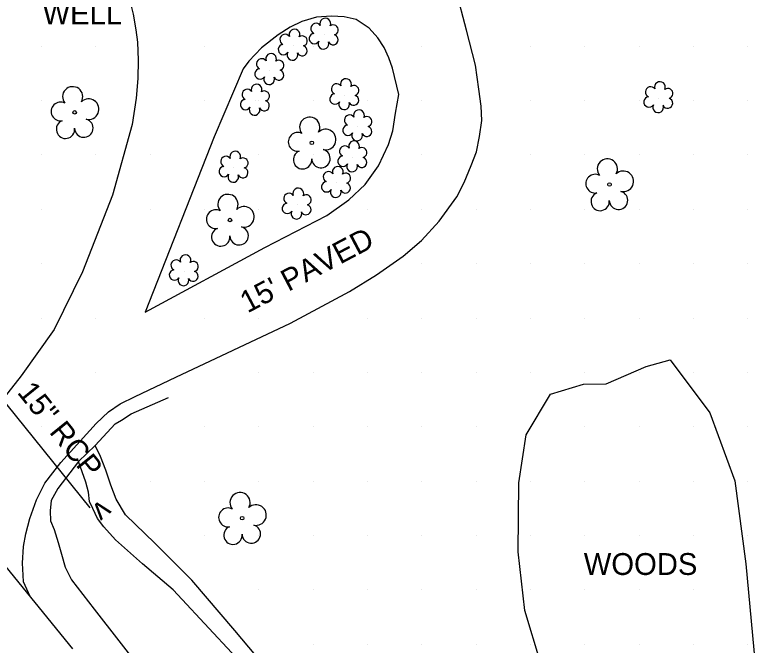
# Model space of a CAD drawing. Extents: x 1548934 to 1561348, y 809680 to 824075.
# Drawn here: x 1552285.1 to 1552421.7, y 809979.7 to 810095.7 of the extents above; entities that cross this region are included whole.
import ezdxf

# ---------------------------------------------------------------- set-up
doc = ezdxf.new("R2010")
doc.units = 0
for name, color, linetype in [('E_NCDOT_Vertical_Profile_Ground_Line', 7, 'Continuous'), ('Exist DTM QL2 LIDAR Elevation Point', 7, 'Continuous'), ('Exist Other Culture Well Text', 7, 'Continuous'), ('Exist Roads EOP Other Text', 7, 'Continuous'), ('Exist Structure Minor Culvert Topo', 7, 'Continuous'), ('Exist Structure Minor Culvert Topo Terminator', 7, 'Continuous'), ('Exist Structure Minor Pipes RCP 15 Inch Text', 7, 'Continuous'), ('Exist Vegetation Shrub CELL', 7, 'Continuous'), ('Exist Vegetation Tree CELL', 7, 'Continuous'), ('Exist Vegetation Woods Line', 7, 'Continuous'), ('Exist Vegetation Woods Line Text', 7, 'Continuous'), ('P_RDY_Paved_Shoulder', 7, 'Continuous'), ('PH Exist DTM Breakline', 7, 'Continuous')]:
    doc.layers.add(name, color=color, linetype=linetype)

msp = doc.modelspace()

# ---------------------------------------------------------------- linework, layer by layer
at = {"layer": 'E_NCDOT_Vertical_Profile_Ground_Line'}
msp.add_line((1552295.81, 809979.05), (1552269.12, 810011.85), dxfattribs=at)
at = {"layer": 'Exist DTM QL2 LIDAR Elevation Point'}
for p, q in [((1552290.04, 810089.94), (1552290.04, 810089.94)), ((1552300.04, 810089.94), (1552300.04, 810089.94)), ((1552320.04, 810089.94), (1552320.04, 810089.94)), ((1552340.05, 810089.94), (1552340.05, 810089.94)), ((1552360.05, 810089.94), (1552360.05, 810089.94)), ((1552380.05, 810089.94), (1552380.05, 810089.94)), ((1552390.05, 810089.94), (1552390.05, 810089.94)), ((1552400.05, 810089.94), (1552400.05, 810089.94)), ((1552410.05, 810089.94), (1552410.05, 810089.94)), ((1552420.05, 810089.94), (1552420.05, 810089.94)), ((1552290.04, 810079.94), (1552290.04, 810079.94)), ((1552300.04, 810079.94), (1552300.04, 810079.94)), ((1552320.04, 810079.94), (1552320.04, 810079.94)), ((1552330.05, 810079.94), (1552330.05, 810079.94)), ((1552340.05, 810079.94), (1552340.05, 810079.94)), ((1552350.05, 810079.94), (1552350.05, 810079.94)), ((1552360.05, 810079.94), (1552360.05, 810079.94)), ((1552380.05, 810079.94), (1552380.05, 810079.94)), ((1552390.05, 810079.94), (1552390.05, 810079.94)), ((1552400.05, 810079.94), (1552400.05, 810079.94)), ((1552410.05, 810079.94), (1552410.05, 810079.94)), ((1552420.05, 810079.94), (1552420.05, 810079.94)), ((1552290.04, 810069.94), (1552290.04, 810069.94)), ((1552300.04, 810069.94), (1552300.04, 810069.94)), ((1552310.04, 810069.94), (1552310.04, 810069.94)), ((1552330.05, 810069.94), (1552330.05, 810069.94)), ((1552340.05, 810069.94), (1552340.05, 810069.94)), ((1552360.05, 810069.94), (1552360.05, 810069.94)), ((1552380.05, 810069.94), (1552380.05, 810069.94)), ((1552390.05, 810069.94), (1552390.05, 810069.94)), ((1552400.05, 810069.94), (1552400.05, 810069.94)), ((1552410.05, 810069.94), (1552410.05, 810069.94)), ((1552420.05, 810069.94), (1552420.05, 810069.94)), ((1552290.04, 810059.94), (1552290.04, 810059.94)), ((1552310.04, 810059.94), (1552310.04, 810059.94)), ((1552320.04, 810059.94), (1552320.04, 810059.94)), ((1552330.05, 810059.94), (1552330.05, 810059.94)), ((1552350.05, 810059.94), (1552350.05, 810059.94)), ((1552360.05, 810059.94), (1552360.05, 810059.94)), ((1552370.05, 810059.94), (1552370.05, 810059.94)), ((1552380.05, 810059.94), (1552380.05, 810059.94)), ((1552390.05, 810059.94), (1552390.05, 810059.94)), ((1552400.05, 810059.94), (1552400.05, 810059.94)), ((1552410.05, 810059.94), (1552410.05, 810059.94)), ((1552420.05, 810059.94), (1552420.05, 810059.94)), ((1552290.04, 810049.94), (1552290.04, 810049.94)), ((1552340.05, 810049.94), (1552340.05, 810049.94)), ((1552360.05, 810049.94), (1552360.05, 810049.94)), ((1552370.05, 810049.94), (1552370.05, 810049.94)), ((1552380.05, 810049.94), (1552380.05, 810049.94)), ((1552390.05, 810049.94), (1552390.05, 810049.94)), ((1552400.05, 810049.94), (1552400.05, 810049.94)), ((1552410.05, 810049.94), (1552410.05, 810049.94)), ((1552420.05, 810049.94), (1552420.05, 810049.94)), ((1552290.04, 810039.93), (1552290.04, 810039.93)), ((1552300.04, 810039.93), (1552300.04, 810039.93)), ((1552320.04, 810039.93), (1552320.04, 810039.93)), ((1552330.05, 810039.93), (1552330.05, 810039.93)), ((1552350.05, 810039.93), (1552350.05, 810039.93)), ((1552360.05, 810039.93), (1552360.05, 810039.93)), ((1552370.05, 810039.93), (1552370.05, 810039.93)), ((1552380.05, 810039.93), (1552380.05, 810039.93)), ((1552390.05, 810039.93), (1552390.05, 810039.93)), ((1552400.05, 810039.93), (1552400.05, 810039.93)), ((1552410.05, 810039.93), (1552410.05, 810039.93)), ((1552420.05, 810039.93), (1552420.05, 810039.93)), ((1552300.04, 810029.93), (1552300.04, 810029.93)), ((1552330.05, 810029.93), (1552330.05, 810029.93)), ((1552340.05, 810029.93), (1552340.05, 810029.93)), ((1552350.05, 810029.93), (1552350.05, 810029.93)), ((1552360.05, 810029.93), (1552360.05, 810029.93)), ((1552370.05, 810029.93), (1552370.05, 810029.93)), ((1552380.05, 810029.93), (1552380.05, 810029.93)), ((1552390.05, 810029.93), (1552390.05, 810029.93)), ((1552400.05, 810029.93), (1552400.05, 810029.93)), ((1552410.05, 810029.93), (1552410.05, 810029.93)), ((1552420.05, 810029.93), (1552420.05, 810029.93)), ((1552290.04, 810019.93), (1552290.04, 810019.93)), ((1552320.04, 810019.93), (1552320.04, 810019.93)), ((1552330.05, 810019.93), (1552330.05, 810019.93)), ((1552340.05, 810019.93), (1552340.05, 810019.93)), ((1552350.05, 810019.93), (1552350.05, 810019.93)), ((1552360.05, 810019.93), (1552360.05, 810019.93)), ((1552370.05, 810019.93), (1552370.05, 810019.93)), ((1552380.05, 810019.93), (1552380.05, 810019.93)), ((1552390.05, 810019.93), (1552390.05, 810019.93)), ((1552400.05, 810019.93), (1552400.05, 810019.93)), ((1552410.05, 810019.93), (1552410.05, 810019.93)), ((1552420.05, 810019.93), (1552420.05, 810019.93)), ((1552310.04, 810009.93), (1552310.04, 810009.93)), ((1552320.04, 810009.93), (1552320.04, 810009.93)), ((1552330.05, 810009.93), (1552330.05, 810009.93)), ((1552340.05, 810009.93), (1552340.05, 810009.93)), ((1552350.05, 810009.93), (1552350.05, 810009.93)), ((1552360.05, 810009.93), (1552360.05, 810009.93)), ((1552370.05, 810009.93), (1552370.05, 810009.93)), ((1552380.05, 810009.93), (1552380.05, 810009.93)), ((1552390.05, 810009.93), (1552390.05, 810009.93)), ((1552400.05, 810009.93), (1552400.05, 810009.93)), ((1552410.05, 810009.93), (1552410.05, 810009.93)), ((1552420.05, 810009.93), (1552420.05, 810009.93)), ((1552320.04, 809999.93), (1552320.04, 809999.93)), ((1552330.05, 809999.93), (1552330.05, 809999.93)), ((1552340.05, 809999.93), (1552340.05, 809999.93)), ((1552350.05, 809999.93), (1552350.05, 809999.93)), ((1552360.05, 809999.93), (1552360.05, 809999.93)), ((1552370.05, 809999.93), (1552370.05, 809999.93)), ((1552380.05, 809999.93), (1552380.05, 809999.93)), ((1552390.05, 809999.93), (1552390.05, 809999.93)), ((1552400.05, 809999.93), (1552400.05, 809999.93)), ((1552410.05, 809999.93), (1552410.05, 809999.93)), ((1552420.05, 809999.93), (1552420.05, 809999.93)), ((1552330.05, 809989.93), (1552330.05, 809989.93)), ((1552340.05, 809989.93), (1552340.05, 809989.93)), ((1552350.05, 809989.93), (1552350.05, 809989.93)), ((1552360.05, 809989.93), (1552360.05, 809989.93)), ((1552370.05, 809989.93), (1552370.05, 809989.93)), ((1552380.05, 809989.93), (1552380.05, 809989.93)), ((1552390.05, 809989.93), (1552390.05, 809989.93)), ((1552400.05, 809989.93), (1552400.05, 809989.93)), ((1552410.05, 809989.93), (1552410.05, 809989.93)), ((1552420.05, 809989.93), (1552420.05, 809989.93)), ((1552340.05, 809979.93), (1552340.05, 809979.93)), ((1552350.05, 809979.93), (1552350.05, 809979.93)), ((1552360.05, 809979.93), (1552360.05, 809979.93)), ((1552370.05, 809979.93), (1552370.05, 809979.93)), ((1552380.05, 809979.93), (1552380.05, 809979.93)), ((1552390.05, 809979.93), (1552390.05, 809979.93)), ((1552400.05, 809979.93), (1552400.05, 809979.93)), ((1552410.05, 809979.93), (1552410.05, 809979.93)), ((1552420.05, 809979.93), (1552420.05, 809979.93))]:
    msp.add_line(p, q, dxfattribs=at)
at = {"layer": 'Exist Structure Minor Culvert Topo'}
msp.add_line((1552299.03, 810005.01), (1552279.48, 810029.19), dxfattribs=at)
at = {"layer": 'Exist Vegetation Shrub CELL'}
for p, q in [((1552342.05, 810092.07), (1552342.05, 810092.07)), ((1552336.36, 810090.04), (1552336.36, 810090.04)), ((1552332.06, 810085.56), (1552332.06, 810085.56)), ((1552345.85, 810080.94), (1552345.85, 810080.94)), ((1552403.63, 810080.39), (1552403.63, 810080.39)), ((1552329.39, 810079.92), (1552329.39, 810079.92)), ((1552348.24, 810075.2), (1552348.24, 810075.2)), ((1552347.33, 810069.5), (1552347.33, 810069.5)), ((1552325.46, 810067.6), (1552325.46, 810067.6)), ((1552344.33, 810064.79), (1552344.33, 810064.79)), ((1552337.08, 810060.81), (1552337.08, 810060.81)), ((1552316.31, 810048.54), (1552316.31, 810048.54))]:
    msp.add_line(p, q, dxfattribs=at)
for centre, radius, start, end in [((1552340.57, 810093.2), 0.968, 35.8908, 245.4216), ((1552342.28, 810094.11), 0.99, 334.8391, 200.4717), ((1552336.59, 810092.08), 0.99, 334.8391, 200.4717), ((1552343.72, 810092.94), 0.929, 284.4567, 126.0861), ((1552334.88, 810091.17), 0.968, 35.8908, 245.4216), ((1552338.03, 810090.91), 0.929, 284.4567, 126.0861), ((1552340.25, 810091.37), 0.955, 95.1099, 327.9534), ((1552343.69, 810091.14), 0.937, 204.9913, 73.4601), ((1552334.56, 810089.34), 0.955, 95.1099, 327.9534), ((1552338, 810089.11), 0.937, 204.9913, 73.4601), ((1552341.92, 810090.39), 0.984, 151.2797, 21.387), ((1552332.29, 810087.6), 0.99, 334.8391, 200.4717), ((1552336.23, 810088.36), 0.984, 151.2797, 21.387), ((1552330.58, 810086.69), 0.968, 35.8908, 245.4216), ((1552333.73, 810086.43), 0.929, 284.4567, 126.0861), ((1552330.26, 810084.85), 0.955, 95.1099, 327.9534), ((1552333.7, 810084.63), 0.937, 204.9913, 73.4601), ((1552331.93, 810083.87), 0.984, 151.2797, 21.387), ((1552346.08, 810082.98), 0.99, 334.8391, 200.4717), ((1552403.85, 810082.43), 0.99, 334.8391, 200.4717), ((1552327.91, 810081.05), 0.968, 35.8908, 245.4216), ((1552329.62, 810081.96), 0.99, 334.8391, 200.4717), ((1552344.37, 810082.07), 0.968, 35.8908, 245.4216), ((1552347.52, 810081.81), 0.929, 284.4567, 126.0861), ((1552402.14, 810081.52), 0.968, 35.8908, 245.4216), ((1552405.3, 810081.26), 0.929, 284.4567, 126.0861), ((1552331.06, 810080.79), 0.929, 284.4567, 126.0861), ((1552344.05, 810080.23), 0.955, 95.1099, 327.9534), ((1552347.49, 810080.01), 0.937, 204.9913, 73.4601), ((1552401.83, 810079.69), 0.955, 95.1099, 327.9534), ((1552327.59, 810079.22), 0.955, 95.1099, 327.9534), ((1552331.03, 810078.99), 0.937, 204.9913, 73.4601), ((1552345.72, 810079.26), 0.984, 151.2797, 21.387), ((1552403.5, 810078.71), 0.984, 151.2797, 21.387), ((1552405.26, 810079.47), 0.937, 204.9913, 73.4601), ((1552329.26, 810078.24), 0.984, 151.2797, 21.387), ((1552348.47, 810077.24), 0.99, 334.8391, 200.4717), ((1552346.76, 810076.33), 0.968, 35.8908, 245.4216), ((1552349.92, 810076.07), 0.929, 284.4567, 126.0861), ((1552346.44, 810074.5), 0.955, 95.1099, 327.9534), ((1552349.88, 810074.27), 0.937, 204.9913, 73.4601), ((1552348.12, 810073.52), 0.984, 151.2797, 21.387), ((1552347.56, 810071.54), 0.99, 334.8391, 200.4717), ((1552345.85, 810070.63), 0.968, 35.8908, 245.4216), ((1552349, 810070.37), 0.929, 284.4567, 126.0861), ((1552323.98, 810068.72), 0.968, 35.8908, 245.4216), ((1552325.69, 810069.64), 0.99, 334.8391, 200.4717), ((1552345.53, 810068.8), 0.955, 95.1099, 327.9534), ((1552348.97, 810068.57), 0.937, 204.9913, 73.4601), ((1552327.14, 810068.46), 0.929, 284.4567, 126.0861), ((1552347.2, 810067.82), 0.984, 151.2797, 21.387), ((1552323.66, 810066.89), 0.955, 95.1099, 327.9534), ((1552327.1, 810066.67), 0.937, 204.9913, 73.4601), ((1552342.85, 810065.91), 0.968, 35.8908, 245.4216), ((1552344.56, 810066.83), 0.99, 334.8391, 200.4717), ((1552325.34, 810065.91), 0.984, 151.2797, 21.387), ((1552346, 810065.66), 0.929, 284.4567, 126.0861), ((1552342.53, 810064.08), 0.955, 95.1099, 327.9534), ((1552345.97, 810063.86), 0.937, 204.9913, 73.4601), ((1552335.59, 810061.94), 0.968, 35.8908, 245.4216), ((1552337.31, 810062.85), 0.99, 334.8391, 200.4717), ((1552344.2, 810063.1), 0.984, 151.2797, 21.387), ((1552338.75, 810061.68), 0.929, 284.4567, 126.0861), ((1552335.28, 810060.11), 0.955, 95.1099, 327.9534), ((1552338.71, 810059.88), 0.937, 204.9913, 73.4601), ((1552336.95, 810059.13), 0.984, 151.2797, 21.387), ((1552314.82, 810049.67), 0.968, 35.8908, 245.4216), ((1552316.53, 810050.58), 0.99, 334.8391, 200.4717), ((1552317.98, 810049.41), 0.929, 284.4567, 126.0861), ((1552314.51, 810047.84), 0.955, 95.1099, 327.9534), ((1552317.94, 810047.62), 0.937, 204.9913, 73.4601), ((1552316.18, 810046.86), 0.984, 151.2797, 21.387)]:
    msp.add_arc(centre, radius, start, end, dxfattribs=at)
at = {"layer": 'Exist Vegetation Tree CELL'}
for p, q in [((1552296.16, 810077.78), (1552296.16, 810077.78)), ((1552339.78, 810072.18), (1552339.78, 810072.18)), ((1552394.56, 810064.5), (1552394.56, 810064.5)), ((1552324.74, 810057.97), (1552324.74, 810057.97)), ((1552326.97, 810003.1), (1552326.97, 810003.1))]:
    msp.add_line(p, q, dxfattribs=at)
for centre in [(1552296.16, 810077.78), (1552339.78, 810072.18), (1552394.56, 810064.5), (1552324.74, 810057.97), (1552326.97, 810003.1)]:
    msp.add_circle(centre, 0.326, dxfattribs=at)
for centre, radius, start, end in [((1552295.78, 810080.65), 1.86, 330.1651, 219.7134), ((1552293.56, 810077.93), 1.73, 62.6636, 279.3457), ((1552298.71, 810078.37), 1.9, 257.1011, 134.1999), ((1552297.84, 810074.88), 1.7, 181.2822, 74.56), ((1552339.4, 810075.06), 1.86, 330.1651, 219.7134), ((1552294.46, 810074.66), 1.69, 111.5671, 6.231), ((1552337.18, 810072.34), 1.73, 62.6636, 279.3457), ((1552342.33, 810072.77), 1.9, 257.1011, 134.1999), ((1552341.46, 810069.28), 1.7, 181.2822, 74.56), ((1552338.08, 810069.06), 1.69, 111.5671, 6.231), ((1552394.17, 810067.37), 1.86, 330.1651, 219.7134), ((1552397.1, 810065.09), 1.9, 257.1011, 134.1999), ((1552391.95, 810064.65), 1.73, 62.6636, 279.3457), ((1552324.35, 810060.84), 1.86, 330.1651, 219.7134), ((1552392.85, 810061.38), 1.69, 111.5671, 6.231), ((1552396.23, 810061.6), 1.7, 181.2822, 74.56), ((1552327.29, 810058.56), 1.9, 257.1011, 134.1999), ((1552322.13, 810058.12), 1.73, 62.6636, 279.3457), ((1552323.03, 810054.85), 1.69, 111.5671, 6.231), ((1552326.41, 810055.07), 1.7, 181.2822, 74.56), ((1552326.59, 810005.97), 1.86, 330.1651, 219.7134), ((1552329.52, 810003.68), 1.9, 257.1011, 134.1999), ((1552324.37, 810003.25), 1.73, 62.6636, 279.3457), ((1552325.27, 809999.97), 1.69, 111.5671, 6.231), ((1552328.65, 810000.2), 1.7, 181.2822, 74.56)]:
    msp.add_arc(centre, radius, start, end, dxfattribs=at)
at = {"layer": 'Exist Vegetation Woods Line'}
msp.add_lwpolyline([(1552381.88, 809976.55), (1552379, 809986.1), (1552377.74, 809996.93), (1552377.88, 810009.64), (1552379.25, 810018.45), (1552383.69, 810025.93), (1552389.8, 810027.77), (1552393.93, 810027.85), (1552401.3, 810031), (1552405.72, 810032.23), (1552413, 810022.52), (1552417.66, 810009.96), (1552419.63, 809994.71), (1552424.82, 809939.32)], dxfattribs=at)
at = {"layer": 'P_RDY_Paved_Shoulder'}
for points in [[(1552299.4, 810156.58), (1552298.01, 810145.79), (1552297.56, 810137.52), (1552297.6, 810132.65), (1552297.99, 810127.86), (1552298.85, 810122.84), (1552299.95, 810117.15), (1552301.72, 810111.42), (1552303.21, 810107.4), (1552304.76, 810103.35), (1552306.13, 810099.07), (1552306.94, 810095.86), (1552307.43, 810092.96), (1552307.69, 810090.69), (1552307.82, 810087.4), (1552307.76, 810084.03), (1552307.46, 810080.42), (1552306.73, 810075.55), (1552303.1, 810062.52), (1552297.6, 810048.45), (1552292.35, 810037.8), (1552286.29, 810029.28), (1552278.9, 810019.9)], [(1552287.98, 809988.68), (1552286.76, 809991.4), (1552286.7, 809992.64), (1552286.57, 809994.84), (1552286.76, 809997.87), (1552287.18, 810000.21), (1552287.87, 810003.04), (1552289.11, 810006.49), (1552290.64, 810009.56), (1552293.62, 810013.36), (1552300.1, 810020.55), (1552302.35, 810022.68), (1552304.51, 810024.16), (1552307.28, 810025.47), (1552314.78, 810029.03), (1552335.85, 810038.96), (1552346.75, 810044.82), (1552351.69, 810047.9), (1552356.61, 810051.3), (1552359.96, 810054.2), (1552363.24, 810057.78), (1552366.47, 810062.22), (1552367.84, 810064.85), (1552369.13, 810067.99), (1552370.09, 810070.53), (1552370.67, 810073.36), (1552371.05, 810076.3), (1552370.94, 810078.89), (1552370.53, 810082.03), (1552369.89, 810086.46), (1552368.25, 810092.9), (1552366.35, 810100.22)], [(1552355.79, 810081.04), (1552354.61, 810085.89), (1552353.98, 810087.8), (1552353.08, 810089.72), (1552351.95, 810091.51), (1552350.32, 810093.29), (1552347.96, 810094.86), (1552345.74, 810095.38), (1552343.4, 810095.48), (1552340.68, 810095.28), (1552337.94, 810094.52), (1552335.79, 810093.48), (1552333.61, 810092.04), (1552330.53, 810089.63), (1552328.21, 810087.21), (1552327.13, 810085.78), (1552321.84, 810073.26), (1552309.11, 810041.03), (1552331.12, 810052.94), (1552342.55, 810058.83), (1552346.58, 810061.69), (1552349.62, 810064.53), (1552352.08, 810067.93), (1552353.91, 810071.87), (1552354.72, 810074.36), (1552355.21, 810077.6), (1552355.79, 810081.04)]]:
    msp.add_lwpolyline(points, dxfattribs=at)
at = {"layer": 'PH Exist DTM Breakline'}
for points in [[(1552299.91, 810016.47), (1552303.6, 810020.45), (1552304.74, 810021.17), (1552306.55, 810022.29), (1552313.42, 810025.31)], [(1552400.44, 809899.51), (1552382.33, 809916.43), (1552375.71, 809923.44), (1552373.44, 809925.92), (1552371.46, 809929.85), (1552368.84, 809934.65), (1552365.65, 809939.82), (1552360.91, 809945.16), (1552351.96, 809952.25), (1552338.82, 809966.74), (1552325.61, 809982.46), (1552317.69, 809991.72), (1552310.93, 809998.52), (1552305.49, 810003.74), (1552303.76, 810006.58), (1552302.79, 810009.18), (1552301.9, 810011.95), (1552300.88, 810014.46), (1552299.91, 810016.47), (1552296.87, 810013.53)], [(1552331.74, 809971.13), (1552321.68, 809981.93), (1552314.27, 809989.93), (1552308.61, 809994.72), (1552303.64, 809999.15), (1552301.5, 810001.52), (1552300.32, 810003.02), (1552299.47, 810004.91), (1552298.85, 810006.2), (1552298.71, 810007.87), (1552298.21, 810009.76), (1552296.87, 810013.53), (1552293.06, 810008.58), (1552291.83, 810006.33), (1552291.63, 810004.46), (1552291.7, 810002.62), (1552292.37, 810001.01), (1552293.11, 809998.66), (1552293.72, 809996.47), (1552294.4, 809994.1), (1552295.55, 809991.77), (1552299.72, 809986.35), (1552308.36, 809975.29)]]:
    msp.add_lwpolyline(points, dxfattribs=at)

# ---------------------------------------------------------------- texts
at = {"layer": 'Exist Other Culture Well Text'}
msp.add_text('WELL', height=4.02, dxfattribs=at).set_placement((1552290.23, 810093.98))
at = {"layer": 'Exist Roads EOP Other Text'}
msp.add_text("15' PAVED", height=4.02, rotation=27.8428, dxfattribs=at).set_placement((1552327.96, 810040.76))
at = {"layer": 'Exist Structure Minor Culvert Topo Terminator'}
msp.add_text('v', height=4, rotation=218.9616, dxfattribs=at).set_placement((1552301.09, 810006.68))
at = {"layer": 'Exist Structure Minor Pipes RCP 15 Inch Text'}
msp.add_text('15" RCP', height=4.02, rotation=308.9616, dxfattribs=at).set_placement((1552285.43, 810026.21))
at = {"layer": 'Exist Vegetation Woods Line Text'}
msp.add_text('WOODS', height=4.02, dxfattribs=at).set_placement((1552389.83, 809992.66))

doc.saveas('drawing.dxf')
